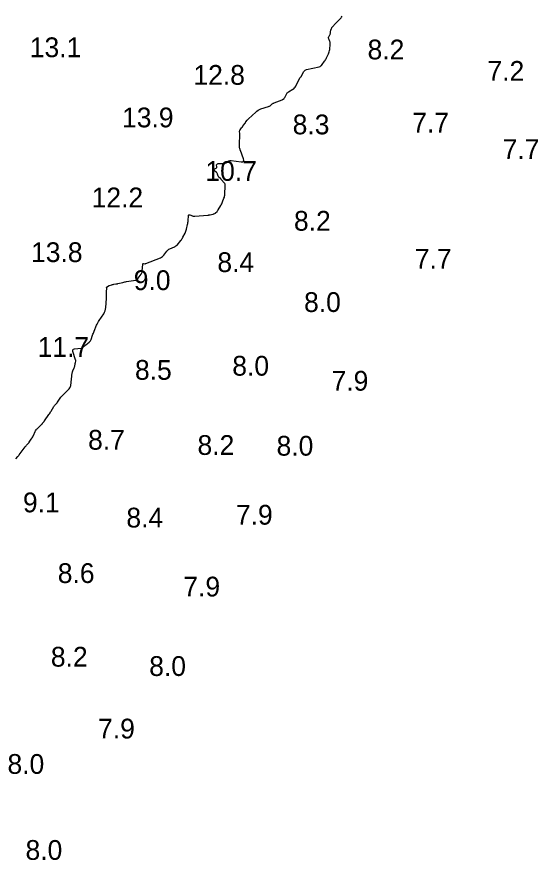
# Model space of a CAD drawing. Extents: x 815352 to 820877, y 582403 to 597439.
# Drawn here: x 820456.5 to 820588.2, y 589267.9 to 589481.2 of the extents above; entities that cross this region are included whole.
import ezdxf

# ---------------------------------------------------------------- set-up
doc = ezdxf.new("R2010")
doc.units = 0
doc.layers.add('V-CONT-EL12', color=7, linetype='Continuous')
doc.layers.add('V-TOPO-SOUN', color=7, linetype='Continuous')

msp = doc.modelspace()

# ---------------------------------------------------------------- linework, layer by layer
at = {"layer": 'V-CONT-EL12'}
msp.add_lwpolyline([(820456.28, 589369.38), (820456.74, 589369.97), (820456.82, 589370.07), (820456.9, 589370.17), (820456.98, 589370.27), (820457.06, 589370.37), (820458.59, 589372.39), (820458.68, 589372.5), (820458.76, 589372.61), (820458.85, 589372.71), (820458.94, 589372.82), (820459.31, 589373.22), (820459.4, 589373.33), (820459.49, 589373.43), (820459.57, 589373.54), (820459.65, 589373.65), (820460.15, 589374.4), (820460.2, 589374.47), (820460.24, 589374.54), (820460.29, 589374.62), (820460.33, 589374.69), (820460.51, 589374.99), (820460.55, 589375.07), (820460.59, 589375.15), (820460.63, 589375.22), (820460.67, 589375.3), (820461.15, 589376.32), (820461.25, 589376.51), (820461.36, 589376.69), (820461.5, 589376.86), (820461.64, 589377.02), (820462.81, 589378.15), (820462.84, 589378.18), (820462.86, 589378.2), (820462.89, 589378.23), (820462.91, 589378.26), (820463, 589378.36), (820463.02, 589378.39), (820463.05, 589378.42), (820463.07, 589378.45), (820463.09, 589378.47), (820463.32, 589378.77), (820463.36, 589378.83), (820463.41, 589378.89), (820463.45, 589378.95), (820463.49, 589379.01), (820464.6, 589380.58), (820464.75, 589380.8), (820464.9, 589381.03), (820465.04, 589381.25), (820465.18, 589381.48), (820465.88, 589382.65), (820465.94, 589382.75), (820466.01, 589382.85), (820466.08, 589382.95), (820466.16, 589383.04), (820466.49, 589383.39), (820466.57, 589383.48), (820466.65, 589383.57), (820466.72, 589383.67), (820466.79, 589383.77), (820467.48, 589384.77), (820467.63, 589384.97), (820467.78, 589385.16), (820467.94, 589385.34), (820468.11, 589385.52), (820469.52, 589386.91), (820469.57, 589386.96), (820469.61, 589387.01), (820469.66, 589387.06), (820469.7, 589387.11), (820469.88, 589387.35), (820469.91, 589387.39), (820469.94, 589387.44), (820469.96, 589387.48), (820469.98, 589387.53), (820470.07, 589387.71), (820470.09, 589387.76), (820470.1, 589387.81), (820470.11, 589387.86), (820470.12, 589387.91), (820470.5, 589391.15), (820470.53, 589391.3), (820470.56, 589391.45), (820470.61, 589391.59), (820470.67, 589391.73), (820470.96, 589392.33), (820471.01, 589392.45), (820471.05, 589392.56), (820471.09, 589392.69), (820471.12, 589392.81), (820471.23, 589393.39), (820471.25, 589393.48), (820471.26, 589393.56), (820471.28, 589393.65), (820471.3, 589393.73), (820471.37, 589394.07), (820471.38, 589394.15), (820471.39, 589394.23), (820471.38, 589394.32), (820471.35, 589394.4), (820470.66, 589396.52), (820470.61, 589396.79), (820470.67, 589396.99), (820470.83, 589397.13), (820471.1, 589397.2), (820472.78, 589397.39), (820472.9, 589397.41), (820473.01, 589397.45), (820473.11, 589397.51), (820473.2, 589397.58), (820473.55, 589397.92), (820473.64, 589398), (820473.73, 589398.08), (820473.83, 589398.16), (820473.92, 589398.23), (820474.8, 589398.92), (820474.96, 589399.07), (820475.1, 589399.23), (820475.21, 589399.42), (820475.29, 589399.62), (820475.65, 589400.72), (820475.74, 589400.97), (820475.83, 589401.22), (820475.92, 589401.47), (820476.02, 589401.72), (820476.63, 589403.18), (820476.77, 589403.5), (820476.93, 589403.81), (820477.11, 589404.12), (820477.3, 589404.41), (820478.44, 589406.09), (820478.66, 589406.46), (820478.82, 589406.84), (820478.93, 589407.24), (820478.99, 589407.66), (820479.17, 589409.95), (820479.18, 589410.09), (820479.18, 589410.22), (820479.18, 589410.36), (820479.17, 589410.5), (820479.14, 589411.06), (820479.13, 589411.19), (820479.13, 589411.33), (820479.13, 589411.47), (820479.14, 589411.61), (820479.21, 589412.55), (820479.21, 589412.58), (820479.21, 589412.6), (820479.21, 589412.63), (820479.2, 589412.65), (820479.17, 589412.76), (820479.16, 589412.78), (820479.17, 589412.8), (820479.18, 589412.82), (820479.19, 589412.84), (820479.61, 589413.11), (820479.69, 589413.16), (820479.77, 589413.2), (820479.85, 589413.24), (820479.94, 589413.27), (820480.51, 589413.45), (820480.63, 589413.48), (820480.76, 589413.52), (820480.88, 589413.54), (820481.01, 589413.56), (820481.54, 589413.63), (820481.67, 589413.64), (820481.8, 589413.67), (820481.93, 589413.69), (820482.06, 589413.72), (820483.26, 589414.03), (820483.51, 589414.09), (820483.75, 589414.14), (820484, 589414.19), (820484.25, 589414.22), (820486.6, 589414.56), (820486.65, 589414.57), (820486.7, 589414.59), (820486.74, 589414.62), (820486.77, 589414.66), (820486.92, 589414.87), (820486.94, 589414.9), (820486.96, 589414.92), (820486.98, 589414.94), (820487.01, 589414.95), (820487.11, 589415.02), (820487.13, 589415.03), (820487.15, 589415.05), (820487.17, 589415.07), (820487.19, 589415.1), (820487.89, 589416.08), (820488, 589416.26), (820488.08, 589416.44), (820488.14, 589416.64), (820488.17, 589416.85), (820488.3, 589418.65), (820488.32, 589418.72), (820488.35, 589418.76), (820488.4, 589418.79), (820488.48, 589418.79), (820488.81, 589418.76), (820488.89, 589418.76), (820488.97, 589418.76), (820489.05, 589418.78), (820489.12, 589418.81), (820492.8, 589420.28), (820493.05, 589420.4), (820493.28, 589420.55), (820493.49, 589420.74), (820493.68, 589420.95), (820494.43, 589421.96), (820494.58, 589422.13), (820494.75, 589422.28), (820494.94, 589422.41), (820495.14, 589422.51), (820496.37, 589423.02), (820496.4, 589423.03), (820496.43, 589423.05), (820496.45, 589423.07), (820496.48, 589423.1), (820496.57, 589423.2), (820496.6, 589423.22), (820496.62, 589423.24), (820496.65, 589423.26), (820496.68, 589423.28), (820496.86, 589423.36), (820496.89, 589423.38), (820496.93, 589423.4), (820496.96, 589423.43), (820496.99, 589423.46), (820497.92, 589424.6), (820498.08, 589424.81), (820498.23, 589425.02), (820498.37, 589425.24), (820498.49, 589425.47), (820499.03, 589426.51), (820499.15, 589426.76), (820499.25, 589427.01), (820499.33, 589427.27), (820499.4, 589427.54), (820499.64, 589428.65), (820499.69, 589428.9), (820499.73, 589429.16), (820499.77, 589429.41), (820499.79, 589429.67), (820499.88, 589430.88), (820499.91, 589431.02), (820499.98, 589431.1), (820500.08, 589431.13), (820500.22, 589431.09), (820500.86, 589430.86), (820501.01, 589430.81), (820501.18, 589430.77), (820501.34, 589430.76), (820501.51, 589430.77), (820504.77, 589431.07), (820504.91, 589431.08), (820505.05, 589431.1), (820505.18, 589431.12), (820505.32, 589431.15), (820506.02, 589431.29), (820506.09, 589431.3), (820506.15, 589431.32), (820506.21, 589431.34), (820506.27, 589431.36), (820506.51, 589431.46), (820506.57, 589431.49), (820506.62, 589431.52), (820506.67, 589431.56), (820506.72, 589431.6), (820507.11, 589432.01), (820507.18, 589432.1), (820507.26, 589432.19), (820507.32, 589432.28), (820507.39, 589432.38), (820508.04, 589433.48), (820508.17, 589433.7), (820508.28, 589433.92), (820508.39, 589434.15), (820508.49, 589434.38), (820508.85, 589435.34), (820508.94, 589435.58), (820509, 589435.82), (820509.04, 589436.07), (820509.07, 589436.32), (820509.19, 589438.49), (820509.18, 589438.69), (820509.13, 589438.88), (820509.05, 589439.06), (820508.93, 589439.22), (820508.24, 589440.02), (820508.17, 589440.1), (820508.1, 589440.17), (820508.02, 589440.24), (820507.94, 589440.31), (820507.62, 589440.57), (820507.54, 589440.64), (820507.48, 589440.72), (820507.43, 589440.8), (820507.4, 589440.9), (820507.24, 589441.43), (820507.2, 589441.54), (820507.14, 589441.65), (820507.07, 589441.75), (820506.98, 589441.84), (820506.38, 589442.37), (820506.31, 589442.45), (820506.29, 589442.52), (820506.32, 589442.59), (820506.4, 589442.66), (820506.85, 589442.93), (820506.93, 589442.99), (820506.98, 589443.06), (820507.01, 589443.14), (820507.02, 589443.24), (820507, 589443.77), (820507, 589443.8), (820507.01, 589443.83), (820507.02, 589443.86), (820507.04, 589443.89), (820507.14, 589444), (820507.16, 589444.02), (820507.18, 589444.04), (820507.2, 589444.05), (820507.23, 589444.06), (820507.34, 589444.09), (820507.36, 589444.09), (820507.39, 589444.1), (820507.42, 589444.1), (820507.45, 589444.1), (820508.75, 589444.09), (820508.9, 589444.1), (820509.05, 589444.13), (820509.19, 589444.18), (820509.32, 589444.26), (820509.99, 589444.74), (820510.04, 589444.77), (820510.09, 589444.79), (820510.15, 589444.82), (820510.21, 589444.83), (820510.44, 589444.89), (820510.5, 589444.9), (820510.56, 589444.9), (820510.63, 589444.9), (820510.69, 589444.9), (820513.23, 589444.58), (820513.58, 589444.58), (820513.78, 589444.69), (820513.85, 589444.92), (820513.78, 589445.26), (820512.99, 589447.43), (820512.96, 589447.53), (820512.93, 589447.62), (820512.91, 589447.72), (820512.88, 589447.81), (820512.79, 589448.22), (820512.78, 589448.31), (820512.76, 589448.39), (820512.76, 589448.47), (820512.75, 589448.56), (820512.74, 589448.9), (820512.74, 589448.98), (820512.74, 589449.07), (820512.74, 589449.15), (820512.75, 589449.24), (820512.84, 589451.15), (820512.84, 589451.28), (820512.84, 589451.41), (820512.84, 589451.54), (820512.83, 589451.67), (820512.79, 589452.18), (820512.79, 589452.31), (820512.82, 589452.43), (820512.86, 589452.54), (820512.93, 589452.64), (820513.31, 589453.11), (820513.4, 589453.23), (820513.49, 589453.34), (820513.57, 589453.46), (820513.65, 589453.58), (820514.1, 589454.23), (820514.17, 589454.33), (820514.25, 589454.44), (820514.32, 589454.54), (820514.4, 589454.64), (820514.71, 589455.05), (820514.79, 589455.15), (820514.87, 589455.25), (820514.96, 589455.34), (820515.05, 589455.43), (820516.89, 589457.14), (820517.18, 589457.39), (820517.49, 589457.6), (820517.83, 589457.77), (820518.18, 589457.91), (820520.1, 589458.54), (820520.24, 589458.59), (820520.37, 589458.65), (820520.49, 589458.72), (820520.61, 589458.81), (820521.06, 589459.18), (820521.17, 589459.27), (820521.29, 589459.34), (820521.42, 589459.41), (820521.56, 589459.47), (820523.57, 589460.24), (820523.64, 589460.27), (820523.7, 589460.3), (820523.76, 589460.34), (820523.81, 589460.39), (820524.03, 589460.58), (820524.08, 589460.64), (820524.13, 589460.69), (820524.17, 589460.75), (820524.2, 589460.81), (820524.64, 589461.68), (820524.73, 589461.84), (820524.84, 589461.98), (820524.97, 589462.1), (820525.13, 589462.21), (820526.27, 589462.89), (820526.5, 589463.05), (820526.7, 589463.23), (820526.87, 589463.45), (820527.01, 589463.69), (820528.04, 589465.78), (820528.06, 589465.83), (820528.1, 589465.87), (820528.13, 589465.91), (820528.17, 589465.95), (820528.34, 589466.09), (820528.38, 589466.13), (820528.41, 589466.17), (820528.44, 589466.21), (820528.47, 589466.26), (820529.05, 589467.38), (820529.18, 589467.57), (820529.33, 589467.71), (820529.51, 589467.82), (820529.71, 589467.89), (820532.89, 589468.61), (820533.13, 589468.68), (820533.34, 589468.8), (820533.53, 589468.95), (820533.69, 589469.14), (820534.28, 589469.98), (820534.42, 589470.19), (820534.55, 589470.4), (820534.68, 589470.63), (820534.79, 589470.86), (820535.28, 589471.9), (820535.38, 589472.15), (820535.47, 589472.41), (820535.53, 589472.68), (820535.57, 589472.95), (820535.72, 589474.29), (820535.73, 589474.46), (820535.72, 589474.63), (820535.68, 589474.8), (820535.62, 589474.96), (820535.31, 589475.68), (820535.27, 589475.8), (820535.26, 589475.92), (820535.28, 589476.04), (820535.33, 589476.16), (820535.62, 589476.69), (820535.67, 589476.78), (820535.7, 589476.87), (820535.72, 589476.96), (820535.74, 589477.06), (820535.77, 589477.45), (820535.78, 589477.55), (820535.8, 589477.64), (820535.82, 589477.74), (820535.85, 589477.83), (820536.02, 589478.31), (820536.07, 589478.41), (820536.12, 589478.51), (820536.19, 589478.61), (820536.26, 589478.7), (820537.07, 589479.55), (820537.23, 589479.71), (820537.38, 589479.87), (820537.54, 589480.03), (820537.69, 589480.19), (820538.32, 589480.82), (820538.47, 589480.99), (820538.59, 589481.17), (820538.69, 589481.36)], dxfattribs=at)

# ---------------------------------------------------------------- texts
at = {"layer": 'V-TOPO-SOUN'}
for s, p in [('13.1 ', (820459.77, 589471.02)), ('8.2', (820545.14, 589470.46)), ('12.8 ', (820501.13, 589464.03)), ('7.2', (820575.45, 589465.05)), ('13.9 ', (820483.09, 589453.27)), ('8.3', (820526.21, 589451.5)), ('7.7', (820556.43, 589451.96)), ('7.7', (820579.29, 589445.26)), ('10.7 ', (820504.15, 589439.72)), ('12.2 ', (820475.41, 589433.03)), ('8.2', (820526.54, 589427.12)), ('13.8 ', (820460.09, 589419.18)), ('8.4', (820507.18, 589416.65)), ('7.7', (820557.08, 589417.51)), ('9.0', (820486.05, 589412.09)), ('8.0', (820529.09, 589406.55)), ('11.7 ', (820461.76, 589395.2)), ('8.0', (820510.95, 589390.44)), ('8.5', (820486.35, 589389.39)), ('7.9', (820536.05, 589386.64)), ('8.7', (820474.5, 589371.71)), ('8.2', (820502.16, 589370.39)), ('8.0', (820522.14, 589370.2)), ('9.1', (820458.04, 589355.86)), ('8.4', (820484.18, 589352.02)), ('7.9', (820511.87, 589352.74)), ('8.6', (820466.84, 589337.98)), ('7.9', (820498.58, 589334.57)), ('8.2', (820465.09, 589316.82)), ('8.0', (820489.95, 589314.46)), ('7.9', (820477.03, 589298.64)), ('8.0', (820454.13, 589289.69)), ('8.0', (820458.69, 589267.93))]:
    msp.add_text(s, height=5, dxfattribs=at).set_placement(p)

doc.saveas('drawing.dxf')
